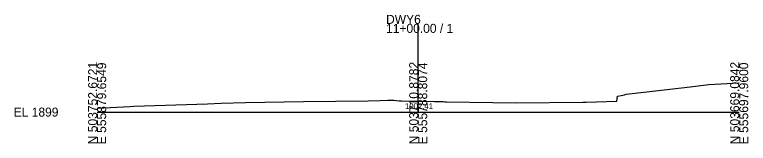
# Model space of a CAD drawing. Extents: x -26 to 1503, y -10 to 1030.
# Drawn here: x -25.7 to 202.8, y 990.3 to 1030.3 of the extents above; entities that cross this region are included whole.
import ezdxf

# ---------------------------------------------------------------- set-up
doc = ezdxf.new("R2010")
doc.units = 0
for name, color, linetype in [('Default', 7, 'Continuous'), ('Exist Cross Section Cell', 7, 'Continuous'), ('Exist XS Center Line Elevation Label', 7, 'Continuous'), ('Exist XS Ground Line', 7, 'Continuous')]:
    doc.layers.add(name, color=color, linetype=linetype)

msp = doc.modelspace()

# ---------------------------------------------------------------- linework, layer by layer
at = {"layer": 'Exist Cross Section Cell'}
for p, q in [((100, 1000), (100, 1027.42)), ((0, 1000), (100, 1000)), ((100, 1000), (200, 1000))]:
    msp.add_line(p, q, dxfattribs=at)
at = {"layer": 'Exist XS Ground Line'}
for p, q in [((171.27, 1006.28), (184.73, 1007.85)), ((184.73, 1007.85), (190.58, 1008.53)), ((190.58, 1008.53), (200, 1009.14)), ((164.83, 1005.52), (171.27, 1006.28)), ((46.25, 1002.96), (64.3, 1003.3)), ((64.3, 1003.3), (84.47, 1003.47)), ((84.47, 1003.47), (88.11, 1003.62)), ((88.11, 1003.62), (90.58, 1003.71)), ((90.58, 1003.71), (92.45, 1003.71)), ((92.45, 1003.71), (94.11, 1003.52)), ((94.11, 1003.52), (94.76, 1003.5)), ((94.76, 1003.5), (100, 1003.41)), ((100, 1003.41), (105.05, 1003.31)), ((105.05, 1003.31), (105.73, 1003.33)), ((105.73, 1003.33), (107.76, 1003.25)), ((152.34, 1003.08), (161.89, 1003.4)), ((161.89, 1003.4), (162.13, 1004.97)), ((162.13, 1004.97), (163.27, 1005.17)), ((163.27, 1005.17), (164.3, 1005.38)), ((164.3, 1005.38), (164.83, 1005.52)), ((0, 1001.22), (10.26, 1001.76)), ((10.26, 1001.76), (11.4, 1001.81)), ((11.4, 1001.81), (34.37, 1002.58)), ((34.37, 1002.58), (38.61, 1002.76)), ((38.61, 1002.76), (46.25, 1002.96)), ((107.76, 1003.25), (108.27, 1003.24)), ((108.27, 1003.24), (108.83, 1003.23)), ((108.83, 1003.23), (123.24, 1003.02)), ((123.24, 1003.02), (130.42, 1002.92)), ((130.42, 1002.92), (151.32, 1003.07)), ((151.32, 1003.07), (152.34, 1003.08))]:
    msp.add_line(p, q, dxfattribs=at)

# ---------------------------------------------------------------- texts
at = {"layer": 'Default'}
msp.add_text('-', height=0.0001, dxfattribs=at).set_placement((0, 1000))
at = {"layer": 'Exist Cross Section Cell'}
for s, p in [('DWY6', (90, 1027.42)), ('11+00.00 / 1', (90, 1024.62)), ('EL 1899', (-26, 998.6))]:
    msp.add_text(s, height=2.8, dxfattribs=at).set_placement(p)
for s, p in [('N 503752.6721', (0, 990)), ('E 555879.6549', (2.8, 990)), ('N 503710.8782', (100, 990)), ('E 555788.8074', (102.8, 990)), ('N 503669.0842', (200, 990)), ('E 555697.9600', (202.8, 990))]:
    msp.add_text(s, height=2.8, rotation=90, dxfattribs=at).set_placement(p)
at = {"layer": 'Exist XS Center Line Elevation Label'}
msp.add_text('1902.41', height=1.8, dxfattribs=at).set_placement((95.91, 1000.96))

doc.saveas('drawing.dxf')
